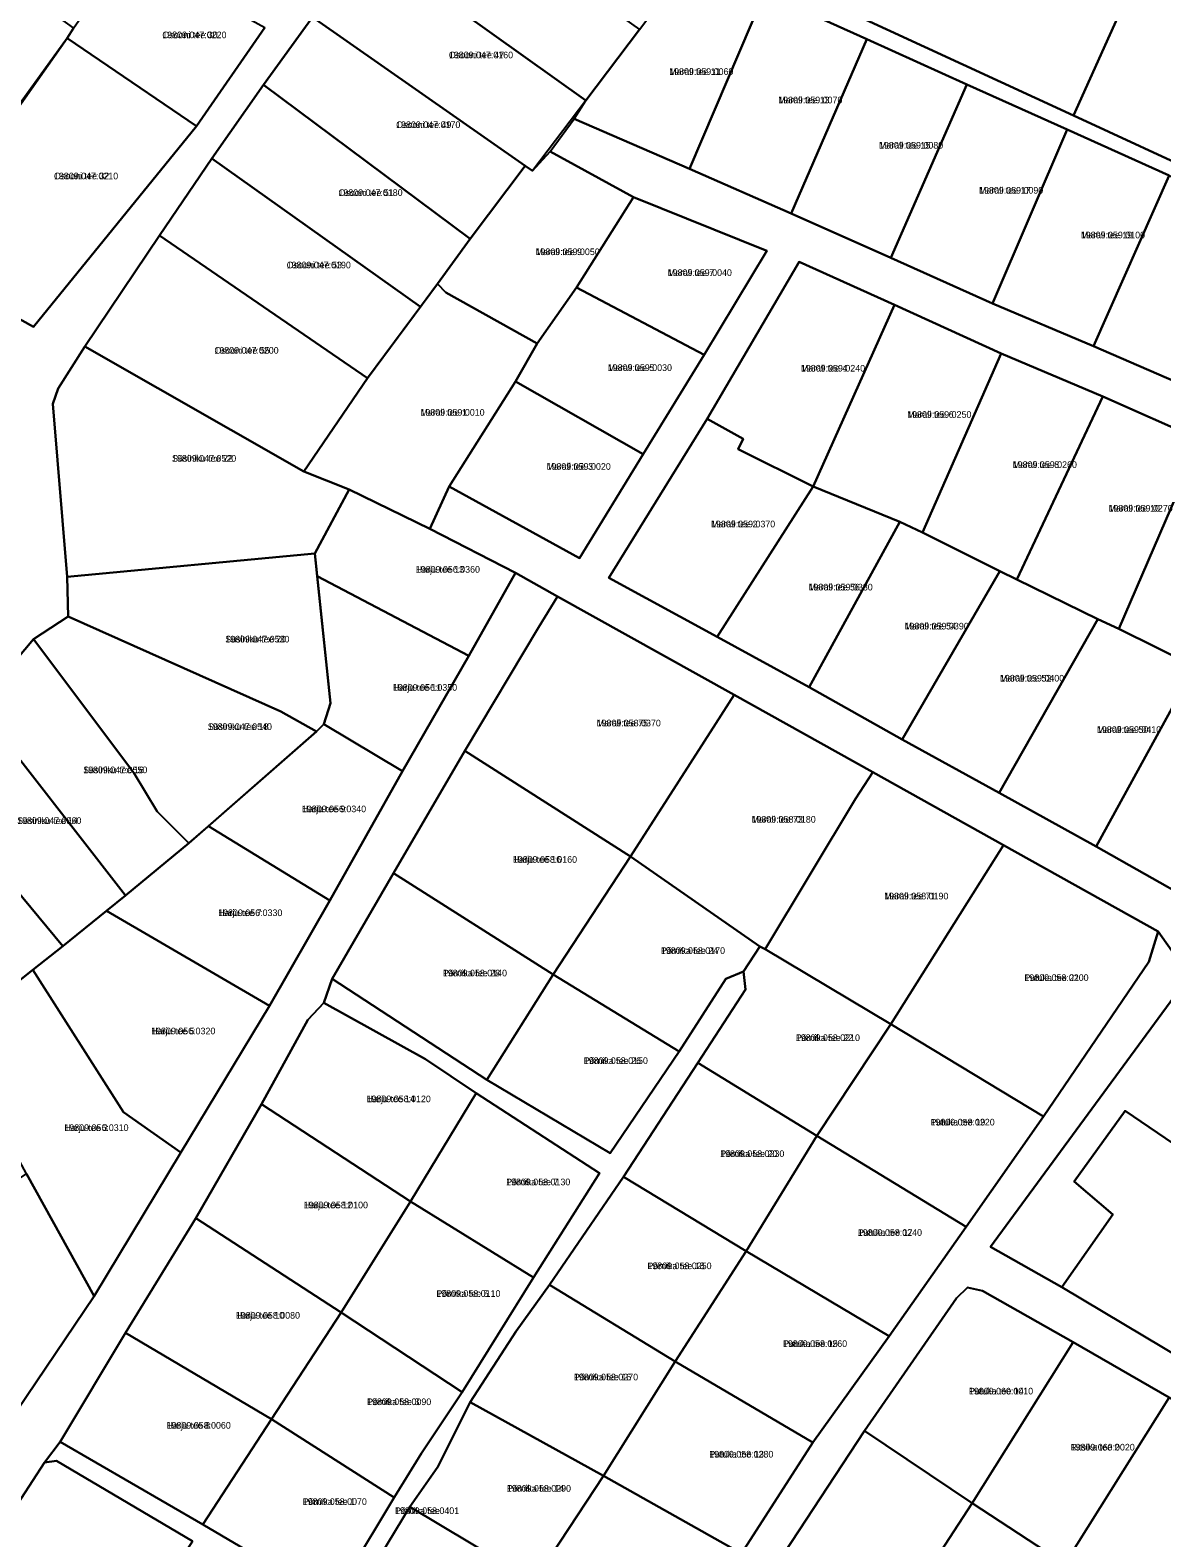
# Model space of a CAD drawing. Extents: x 516875 to 535633, y 6574491 to 6593094.
# Drawn here: x 521977.7 to 522233.5, y 6587757.1 to 6588097.9 of the extents above; entities that cross this region are included whole.
import ezdxf

# ---------------------------------------------------------------- set-up
doc = ezdxf.new("R2010")
doc.units = 0
for name, color, linetype in [('L_AADRESS', 7, 'Continuous'), ('PIIR', 7, 'Continuous'), ('TUNNUS', 7, 'Continuous')]:
    doc.layers.add(name, color=color, linetype=linetype)

msp = doc.modelspace()

# ---------------------------------------------------------------- linework, layer by layer
at = {"layer": 'PIIR'}
for points in [[(522115.41, 6588098.09), (522103.31, 6588082), (522054.22, 6588117.03), (522065.34, 6588133.64)], [(522149.7, 6588121.84), (522155.87, 6588130.09), (522198.27, 6588109.97), (522200.79, 6588117.55), (522226.35, 6588108.22), (522225.49, 6588105.33), (522213.47, 6588078.63), (522129.78, 6588117.27), (522138.23, 6588130.17)], [(521987.51, 6588098.39), (521986.11, 6588096.1), (521972.57, 6588077.42), (521944.66, 6588097.83), (521959.43, 6588118.64)], [(522103.31, 6588082), (522091.23, 6588066.09), (522089.56, 6588067.27), (522041.53, 6588100.82), (522054.22, 6588117.03)], [(522030.73, 6588098.49), (522015.31, 6588076.21), (521986.11, 6588096.1), (521987.51, 6588098.39), (521996.37, 6588111.18), (521999.11, 6588115.98)], [(522143.64, 6588106.38), (522126.74, 6588066.59), (522100.63, 6588077.88), (522103.31, 6588082), (522115.41, 6588098.09), (522127.32, 6588113.93)], [(522143.64, 6588106.38), (522166.8, 6588095.85), (522149.73, 6588056.5), (522126.74, 6588066.59)], [(522250.51, 6588095.21), (522253.6, 6588093.82), (522244.48, 6588064.28), (522213.47, 6588078.63), (522225.49, 6588105.33)], [(522089.56, 6588067.27), (522077.12, 6588050.77), (522030.44, 6588085.53), (522041.53, 6588100.82)], [(522015.31, 6588076.21), (521978.5, 6588030.89), (521950.91, 6588046.25), (521986.11, 6588096.1)], [(522166.8, 6588095.85), (522189.38, 6588085.67), (522172.24, 6588046.49), (522149.73, 6588056.5)], [(522189.38, 6588085.67), (522212.08, 6588075.43), (522195.21, 6588036.14), (522172.24, 6588046.49)], [(522077.12, 6588050.77), (522069.81, 6588040.58), (522065.92, 6588035.35), (522018.8, 6588068.87), (522030.44, 6588085.53)], [(522212.08, 6588075.43), (522235.1, 6588065.06), (522218.02, 6588026.45), (522195.21, 6588036.14)], [(522065.92, 6588035.35), (522053.98, 6588019.28), (522006.92, 6588051.47), (522018.8, 6588068.87)], [(522069.81, 6588040.58), (522077.12, 6588050.77), (522089.56, 6588067.27), (522091.23, 6588066.09), (522095.2, 6588070.5), (522114.05, 6588060.17), (522101.18, 6588039.72), (522092.27, 6588027.09), (522071.63, 6588038.65)], [(522235.1, 6588065.06), (522257.8, 6588054.82), (522240.8, 6588016.65), (522218.02, 6588026.45)], [(522114.05, 6588060.17), (522144.18, 6588048.03), (522130.04, 6588024.55), (522101.18, 6588039.72)], [(522053.98, 6588019.28), (522039.57, 6587998.12), (521990.05, 6588026.38), (522006.92, 6588051.47)], [(522173.08, 6588035.84), (522154.7, 6587994.73), (522137.7, 6588003.24), (522138.85, 6588005.54), (522130.72, 6588010.04), (522151.51, 6588045.55)], [(522071.63, 6588038.65), (522092.27, 6588027.09), (522087.37, 6588018.5), (522072.41, 6587994.79), (522068.02, 6587985.17), (522049.85, 6587994.05), (522039.57, 6587998.12), (522053.98, 6588019.28), (522069.81, 6588040.58)], [(522092.27, 6588027.09), (522101.18, 6588039.72), (522130.04, 6588024.55), (522116.22, 6588002.05), (522087.37, 6588018.5)], [(522154.7, 6587994.73), (522173.08, 6588035.84), (522197.13, 6588024.83), (522179.41, 6587984.38), (522174.29, 6587986.8)], [(522039.57, 6587998.12), (522049.85, 6587994.05), (522042.02, 6587979.6), (521986.11, 6587974.36), (521982.88, 6588013.46), (521984.03, 6588016.93), (521990.05, 6588026.38)], [(522179.41, 6587984.38), (522197.13, 6588024.83), (522220.14, 6588015.08), (522200.67, 6587973.78), (522196.85, 6587975.59)], [(522087.37, 6588018.5), (522116.22, 6588002.05), (522101.89, 6587978.59), (522072.41, 6587994.79)], [(522200.67, 6587973.78), (522220.14, 6588015.08), (522242.17, 6588005.32), (522223.73, 6587962.6), (522219.03, 6587964.81)], [(522130.72, 6588010.04), (522138.85, 6588005.54), (522137.7, 6588003.24), (522154.7, 6587994.73), (522132.95, 6587960.76), (522108.48, 6587974.12)], [(522223.73, 6587962.6), (522242.17, 6588005.32), (522265.71, 6587994.89), (522246.46, 6587951.4), (522240.91, 6587954.05)], [(522042.02, 6587979.6), (522049.85, 6587994.05), (522068.02, 6587985.17), (522087.37, 6587975.22), (522076.84, 6587956.5), (522042.57, 6587974.48)], [(522132.95, 6587960.76), (522154.7, 6587994.73), (522174.29, 6587986.8), (522153.8, 6587949.39)], [(522153.8, 6587949.39), (522174.29, 6587986.8), (522179.41, 6587984.38), (522196.85, 6587975.59), (522174.75, 6587937.6)], [(522042.02, 6587979.6), (522045.61, 6587945.76), (522044.09, 6587941.07), (522042.44, 6587939.41), (522034.39, 6587943.9), (521986.32, 6587965.38), (521986.11, 6587974.36)], [(522045.61, 6587945.76), (522042.57, 6587974.48), (522076.84, 6587956.5), (522061.87, 6587930.4), (522044.09, 6587941.07)], [(522174.75, 6587937.6), (522196.85, 6587975.59), (522200.67, 6587973.78), (522219.03, 6587964.81), (522196.72, 6587925.49)], [(522136.81, 6587947.64), (522132.65, 6587941.17), (522113.37, 6587911.15), (522075.92, 6587935), (522092.63, 6587962.87), (522096.86, 6587969.92)], [(522034.39, 6587943.9), (522042.44, 6587939.41), (522013.58, 6587914.11), (522006.43, 6587921.27), (522001.14, 6587930.06), (521978.46, 6587960.29), (521986.32, 6587965.38)], [(522196.72, 6587925.49), (522219.03, 6587964.81), (522223.73, 6587962.6), (522240.91, 6587954.05), (522218.65, 6587913.4)], [(522001.14, 6587930.06), (522006.43, 6587921.27), (522013.58, 6587914.11), (521999.3, 6587902.28), (521965.81, 6587945.26), (521978.46, 6587960.29)], [(522218.65, 6587913.4), (522240.91, 6587954.05), (522246.46, 6587951.4), (522264.65, 6587942.49), (522240.49, 6587901.06)], [(522168.12, 6587930.17), (522164.21, 6587924.14), (522143.79, 6587890.15), (522142.61, 6587890.82), (522113.37, 6587911.15), (522132.65, 6587941.17), (522136.81, 6587947.64)], [(521999.3, 6587902.28), (521994.99, 6587898.82), (521985.07, 6587890.85), (521950.29, 6587932.81), (521965.81, 6587945.26)], [(522042.44, 6587939.41), (522044.09, 6587941.07), (522061.87, 6587930.4), (522045.48, 6587901.21), (522018.02, 6587917.99)], [(521950.29, 6587932.81), (521985.07, 6587890.85), (521978.31, 6587885.48), (521959.17, 6587870.27), (521922.47, 6587889.89), (521944.55, 6587935.02)], [(522113.37, 6587911.15), (522095.92, 6587884.43), (522059.83, 6587907.39), (522075.92, 6587935)], [(522197.65, 6587913.7), (522193.67, 6587907.37), (522172.2, 6587873.25), (522143.79, 6587890.15), (522164.21, 6587924.14), (522168.12, 6587930.17)], [(521999.3, 6587902.28), (522013.58, 6587914.11), (522018.02, 6587917.99), (522045.48, 6587901.21), (522031.82, 6587877.34), (521994.99, 6587898.82)], [(522232.61, 6587894.19), (522230.56, 6587887.33), (522206.72, 6587852.32), (522172.2, 6587873.25), (522193.67, 6587907.37), (522197.65, 6587913.7)], [(522142.61, 6587890.82), (522138.95, 6587885.1), (522134.96, 6587883.47), (522124.37, 6587867.07), (522095.92, 6587884.43), (522113.37, 6587911.15)], [(522095.92, 6587884.43), (522080.93, 6587860.66), (522045.99, 6587883.49), (522059.83, 6587907.39)], [(521978.31, 6587885.48), (521985.07, 6587890.85), (521994.99, 6587898.82), (522031.82, 6587877.34), (522011.74, 6587844.22), (521998.81, 6587853.37)], [(522143.79, 6587890.15), (522172.2, 6587873.25), (522155.53, 6587848.02), (522128.6, 6587864.51), (522139.38, 6587881.04), (522138.95, 6587885.1), (522142.61, 6587890.82)], [(521963.94, 6587863.34), (521959.17, 6587870.27), (521978.31, 6587885.48), (521998.81, 6587853.37), (522011.74, 6587844.22), (521992.16, 6587811.71), (521976.87, 6587839.43)], [(522124.37, 6587867.07), (522108.82, 6587844.04), (522080.93, 6587860.66), (522095.92, 6587884.43)], [(522067.1, 6587865.33), (522078.5, 6587857.65), (522063.64, 6587833.12), (522030.03, 6587855.16), (522040.48, 6587874.24), (522044.08, 6587878.05)], [(522206.72, 6587852.32), (522189.26, 6587827.41), (522155.53, 6587848.02), (522172.2, 6587873.25)], [(522155.53, 6587848.02), (522139.56, 6587821.89), (522111.81, 6587838.75), (522128.6, 6587864.51)], [(522106.41, 6587839.54), (522091.49, 6587815.97), (522063.64, 6587833.12), (522078.5, 6587857.65)], [(522063.64, 6587833.12), (522048.03, 6587808.03), (522015.16, 6587829.39), (522030.03, 6587855.16)], [(522261.45, 6587828.95), (522254.85, 6587817.16), (522261.85, 6587815.32), (522247.87, 6587791.69), (522210.86, 6587813.8), (522222.39, 6587830.21), (522213.64, 6587837.69), (522225.14, 6587853.62)], [(522189.26, 6587827.41), (522171.84, 6587802.74), (522139.56, 6587821.89), (522155.53, 6587848.02)], [(521940.47, 6587775.96), (521940.06, 6587795.22), (521933.27, 6587810.42), (521976.87, 6587839.43), (521992.16, 6587811.71), (521957.13, 6587759.89)], [(522139.56, 6587821.89), (522123.47, 6587796.94), (522095.06, 6587814.32), (522111.81, 6587838.75)], [(522091.49, 6587815.97), (522075.35, 6587790.05), (522048.03, 6587808.03), (522063.64, 6587833.12)], [(522048.03, 6587808.03), (522032.23, 6587783.92), (521999.29, 6587803.43), (522015.16, 6587829.39)], [(522171.84, 6587802.74), (522154.6, 6587778.65), (522123.47, 6587796.94), (522139.56, 6587821.89)], [(522123.47, 6587796.94), (522107.31, 6587771.11), (522077.19, 6587787.78), (522087.52, 6587803.81), (522095.06, 6587814.32)], [(522189.51, 6587813.74), (522192.93, 6587812.95), (522213.44, 6587801.31), (522190.57, 6587764.93), (522166.3, 6587781.34), (522187.07, 6587811.27)], [(522075.35, 6587790.05), (522066.14, 6587776.23), (522060.02, 6587766.2), (522032.23, 6587783.92), (522048.03, 6587808.03)], [(522032.23, 6587783.92), (522016.72, 6587760.15), (521984.5, 6587778.84), (521999.29, 6587803.43)], [(522235.12, 6587788.87), (522211.51, 6587751.23), (522190.57, 6587764.93), (522213.44, 6587801.31)], [(522154.6, 6587778.65), (522138.49, 6587753.6), (522107.31, 6587771.11), (522123.47, 6587796.94)], [(522107.31, 6587771.11), (522091.61, 6587747.31), (522063.55, 6587764.14), (522069.82, 6587773.13), (522077.19, 6587787.78)], [(522258.91, 6587775.22), (522229.27, 6587734.17), (522208.55, 6587745.93), (522211.51, 6587751.23), (522235.12, 6587788.87)], [(522060.02, 6587766.2), (522049.63, 6587749.04), (522046.33, 6587746.17), (522042.07, 6587745.19), (522016.72, 6587760.15), (522032.23, 6587783.92)], [(522190.57, 6587764.93), (522164.91, 6587725.47), (522141.48, 6587743.59), (522166.3, 6587781.34)], [(522014.39, 6587756.34), (521999.62, 6587733.38), (521967.73, 6587753.77), (521980.96, 6587774.11), (521983.66, 6587774.51)], [(522138.49, 6587753.6), (522123.41, 6587728.29), (522091.61, 6587747.31), (522107.31, 6587771.11)], [(522091.61, 6587747.31), (522075.13, 6587722.01), (522048.18, 6587738.7), (522063.55, 6587764.14)], [(522211.51, 6587751.23), (522208.55, 6587745.93), (522184.96, 6587710.01), (522164.91, 6587725.47), (522190.57, 6587764.93)]]:
    msp.add_lwpolyline(points, close=True, dxfattribs=at)
for points in [[(521959.43, 6588118.64), (521944.66, 6588097.83), (521924.74, 6588070.17), (521922.54, 6588062.23), (521950.91, 6588046.25), (521978.5, 6588030.89), (522015.31, 6588076.21), (522030.73, 6588098.49)], [(522235.1, 6588065.06), (522212.08, 6588075.43), (522189.38, 6588085.67), (522166.8, 6588095.85), (522143.64, 6588106.38), (522127.32, 6588113.93), (522129.78, 6588117.27), (522213.47, 6588078.63), (522244.48, 6588064.28)], [(522041.53, 6588100.82), (522030.44, 6588085.53), (522018.8, 6588068.87), (522006.92, 6588051.47), (521990.05, 6588026.38), (521984.03, 6588016.93), (521982.88, 6588013.46), (521986.11, 6587974.36), (521986.32, 6587965.38), (521978.46, 6587960.29), (521965.81, 6587945.26)], [(522261.45, 6587828.95), (522225.14, 6587853.62), (522213.64, 6587837.69), (522222.39, 6587830.21), (522210.86, 6587813.8), (522194.78, 6587822.92), (522239.75, 6587884.12), (522232.61, 6587894.19), (522197.65, 6587913.7), (522168.12, 6587930.17), (522136.81, 6587947.64), (522096.86, 6587969.92), (522087.37, 6587975.22), (522068.02, 6587985.17), (522072.41, 6587994.79), (522101.89, 6587978.59), (522116.22, 6588002.05), (522130.04, 6588024.55), (522144.18, 6588048.03), (522114.05, 6588060.17), (522095.2, 6588070.5), (522100.63, 6588077.88), (522126.74, 6588066.59), (522149.73, 6588056.5), (522172.24, 6588046.49), (522195.21, 6588036.14), (522218.02, 6588026.45), (522240.8, 6588016.65)], [(522242.17, 6588005.32), (522220.14, 6588015.08), (522197.13, 6588024.83), (522173.08, 6588035.84), (522151.51, 6588045.55), (522130.72, 6588010.04), (522108.48, 6587974.12), (522132.95, 6587960.76), (522153.8, 6587949.39), (522174.75, 6587937.6), (522196.72, 6587925.49), (522218.65, 6587913.4), (522240.49, 6587901.06)], [(521940.87, 6587734.77), (521957.13, 6587759.89), (521992.16, 6587811.71), (522011.74, 6587844.22), (522031.82, 6587877.34), (522045.48, 6587901.21), (522061.87, 6587930.4), (522076.84, 6587956.5), (522087.37, 6587975.22), (522096.86, 6587969.92), (522092.63, 6587962.87), (522075.92, 6587935), (522059.83, 6587907.39), (522045.99, 6587883.49), (522044.08, 6587878.05), (522040.48, 6587874.24), (522030.03, 6587855.16), (522015.16, 6587829.39), (521999.29, 6587803.43), (521984.5, 6587778.84), (521980.96, 6587774.11), (521967.73, 6587753.77)], [(522138.49, 6587753.6), (522154.6, 6587778.65), (522171.84, 6587802.74), (522189.26, 6587827.41), (522206.72, 6587852.32), (522230.56, 6587887.33), (522232.61, 6587894.19), (522239.75, 6587884.12), (522194.78, 6587822.92), (522210.86, 6587813.8), (522247.87, 6587791.69), (522269.54, 6587779.16), (522290.74, 6587766.33), (522312.11, 6587753.9)], [(522049.63, 6587749.04), (522060.02, 6587766.2), (522066.14, 6587776.23), (522075.35, 6587790.05), (522091.49, 6587815.97), (522106.41, 6587839.54), (522078.5, 6587857.65), (522067.1, 6587865.33), (522044.08, 6587878.05), (522045.99, 6587883.49), (522080.93, 6587860.66), (522108.82, 6587844.04), (522124.37, 6587867.07), (522134.96, 6587883.47), (522138.95, 6587885.1), (522139.38, 6587881.04), (522128.6, 6587864.51), (522111.81, 6587838.75), (522095.06, 6587814.32), (522087.52, 6587803.81), (522077.19, 6587787.78), (522069.82, 6587773.13), (522063.55, 6587764.14), (522048.18, 6587738.7)], [(522300.31, 6587750.73), (522278.58, 6587763.23), (522258.91, 6587775.22), (522235.12, 6587788.87), (522213.44, 6587801.31), (522192.93, 6587812.95), (522189.51, 6587813.74), (522187.07, 6587811.27), (522166.3, 6587781.34), (522141.48, 6587743.59)], [(522014.39, 6587756.34), (521983.66, 6587774.51), (521980.96, 6587774.11), (521984.5, 6587778.84), (522016.72, 6587760.15), (522042.07, 6587745.19)]]:
    msp.add_lwpolyline(points, dxfattribs=at)

# ---------------------------------------------------------------- texts
at = {"layer": 'L_AADRESS'}
for s, p in [('Osooni tee 30', (522007.59, 6588096.1)), ('Osooni tee 47', (522072.35, 6588091.56)), ('Marali tee 11', (522122.14, 6588087.81)), ('Marali tee 13', (522146.77, 6588081.38)), ('Osooni tee 49', (522060.43, 6588075.79)), ('Marali tee 15', (522169.55, 6588071.15)), ('Osooni tee 32', (521983.11, 6588064.21)), ('Osooni tee 51', (522047.39, 6588060.44)), ('Marali tee 17', (522192.16, 6588060.97)), ('Marali tee 19', (522215.16, 6588050.86)), ('Marali tee 9', (522091.93, 6588047.07)), ('Osooni tee 53', (522035.69, 6588044.08)), ('Marali tee 7', (522121.8, 6588042.36)), ('Osooni tee 55', (522019.37, 6588024.79)), ('Marali tee 5', (522108.26, 6588020.88)), ('Marali tee 4', (522151.9, 6588020.75)), ('Marali tee 1', (522065.92, 6588010.77)), ('Marali tee 6', (522175.92, 6588010.29)), ('Süsiniku tee 22', (522009.79, 6588000.37)), ('Marali tee 8', (522199.77, 6587998.96)), ('Marali tee 3', (522094.43, 6587998.54)), ('Marali tee 10', (522221.42, 6587989.1)), ('Marali tee 2', (522131.59, 6587985.53)), ('Harju tee 13', (522064.87, 6587975.28)), ('Marali tee 56', (522153.62, 6587971.27)), ('Marali tee 54', (522175.32, 6587962.45)), ('Süsiniku tee 20', (522021.81, 6587959.51)), ('Harju tee 11', (522059.71, 6587948.59)), ('Marali tee 52', (522196.89, 6587950.68)), ('Süsiniku tee 18', (522017.86, 6587939.74)), ('Marali tee 75', (522105.74, 6587940.54)), ('Marali tee 50', (522218.81, 6587939.07)), ('Süsiniku tee 16', (521989.7, 6587929.96)), ('Harju tee 9', (522039.14, 6587921.14)), ('Süsiniku tee 14', (521974.79, 6587918.49)), ('Marali tee 73', (522140.74, 6587918.78)), ('Harju tee 16', (522086.81, 6587909.71)), ('Marali tee 71', (522170.72, 6587901.43)), ('Harju tee 7', (522020.21, 6587897.66)), ('Põrnika tee 24', (522120.25, 6587889.11)), ('Põrnika tee 28', (522070.98, 6587884.03)), ('Putuka tee 21', (522202.41, 6587882.99)), ('Harju tee 5', (522005.07, 6587870.94)), ('Põrnika tee 22', (522150.74, 6587869.42)), ('Põrnika tee 26', (522102.82, 6587864.24)), ('Harju tee 14', (522053.76, 6587855.59)), ('Harju tee 3', (521985.46, 6587849.08)), ('Putuka tee 19', (522181.19, 6587850.33)), ('Põrnika tee 20', (522133.65, 6587843.2)), ('Põrnika tee 7', (522085.28, 6587836.81)), ('Harju tee 12', (522039.56, 6587831.6)), ('Putuka tee 17', (522164.76, 6587825.38)), ('Põrnika tee 18', (522117.21, 6587817.85)), ('Põrnika tee 5', (522069.5, 6587811.59)), ('Harju tee 10', (522024.2, 6587806.66)), ('Putuka tee 15', (522147.84, 6587800.27)), ('Põrnika tee 16', (522100.6, 6587792.71)), ('Putuka tee 14', (522189.87, 6587789.53)), ('Põrnika tee 3', (522053.86, 6587787.12)), ('Harju tee 8', (522008.56, 6587781.79)), ('Putuka tee 13', (522131.17, 6587775.27)), ('Ritsika tee 2', (522212.84, 6587776.86)), ('Põrnika tee 14', (522085.44, 6587767.54)), ('Põrnika tee 1', (522039.31, 6587764.56)), ('Põrnika tee', (522060.17, 6587762.5))]:
    msp.add_text(s, height=1.5, dxfattribs=at).set_placement(p)
at = {"layer": 'TUNNUS'}
for s, p in [('19809:047:0220', (522007.59, 6588096.1)), ('19809:047:0160', (522072.35, 6588091.56)), ('19809:059:0060', (522122.14, 6588087.81)), ('19809:059:0070', (522146.77, 6588081.38)), ('19809:047:0170', (522060.43, 6588075.79)), ('19809:059:0080', (522169.55, 6588071.15)), ('19809:047:0210', (521983.11, 6588064.21)), ('19809:047:0180', (522047.39, 6588060.44)), ('19809:059:0090', (522192.16, 6588060.97)), ('19809:059:0100', (522215.16, 6588050.86)), ('19809:059:0050', (522091.93, 6588047.07)), ('19809:047:0190', (522035.69, 6588044.08)), ('19809:059:0040', (522121.8, 6588042.36)), ('19809:047:0200', (522019.37, 6588024.79)), ('19809:059:0030', (522108.26, 6588020.88)), ('19809:059:0240', (522151.9, 6588020.75)), ('19809:059:0010', (522065.92, 6588010.77)), ('19809:059:0250', (522175.92, 6588010.29)), ('19809:047:0520', (522009.79, 6588000.37)), ('19809:059:0260', (522199.77, 6587998.96)), ('19809:059:0020', (522094.43, 6587998.54)), ('19809:059:0270', (522221.42, 6587989.1)), ('19809:059:0370', (522131.59, 6587985.53)), ('19809:056:0360', (522064.87, 6587975.28)), ('19809:059:0380', (522153.62, 6587971.27)), ('19809:059:0390', (522175.32, 6587962.45)), ('19809:047:0530', (522021.81, 6587959.51)), ('19809:056:0350', (522059.71, 6587948.59)), ('19809:059:0400', (522196.89, 6587950.68)), ('19809:047:0540', (522017.86, 6587939.74)), ('19809:058:0370', (522105.74, 6587940.54)), ('19809:059:0410', (522218.81, 6587939.07)), ('19809:047:0550', (521989.7, 6587929.96)), ('19809:056:0340', (522039.14, 6587921.14)), ('19809:047:0560', (521974.79, 6587918.49)), ('19809:058:0180', (522140.74, 6587918.78)), ('19809:058:0160', (522086.81, 6587909.71)), ('19809:058:0190', (522170.72, 6587901.43)), ('19809:056:0330', (522020.21, 6587897.66)), ('19809:058:0170', (522120.25, 6587889.11)), ('19809:058:0140', (522070.98, 6587884.03)), ('19809:058:0200', (522202.41, 6587882.99)), ('19809:056:0320', (522005.07, 6587870.94)), ('19809:058:0210', (522150.74, 6587869.42)), ('19809:058:0150', (522102.82, 6587864.24)), ('19809:058:0120', (522053.76, 6587855.59)), ('19809:056:0310', (521985.46, 6587849.08)), ('19809:058:0220', (522181.19, 6587850.33)), ('19809:058:0230', (522133.65, 6587843.2)), ('19809:058:0130', (522085.28, 6587836.81)), ('19809:058:0100', (522039.56, 6587831.6)), ('19809:058:0240', (522164.76, 6587825.38)), ('19809:058:0250', (522117.21, 6587817.85)), ('19809:058:0110', (522069.5, 6587811.59)), ('19809:058:0080', (522024.2, 6587806.66)), ('19809:058:0260', (522147.84, 6587800.27)), ('19809:058:0270', (522100.6, 6587792.71)), ('19809:060:0010', (522189.87, 6587789.53)), ('19809:058:0090', (522053.86, 6587787.12)), ('19809:058:0060', (522008.56, 6587781.79)), ('19809:058:0280', (522131.17, 6587775.27)), ('19809:060:0020', (522212.84, 6587776.86)), ('19809:058:0290', (522085.44, 6587767.54)), ('19809:058:0070', (522039.31, 6587764.56)), ('19809:058:0401', (522060.17, 6587762.5))]:
    msp.add_text(s, height=1.5, dxfattribs=at).set_placement(p)

doc.saveas('drawing.dxf')
